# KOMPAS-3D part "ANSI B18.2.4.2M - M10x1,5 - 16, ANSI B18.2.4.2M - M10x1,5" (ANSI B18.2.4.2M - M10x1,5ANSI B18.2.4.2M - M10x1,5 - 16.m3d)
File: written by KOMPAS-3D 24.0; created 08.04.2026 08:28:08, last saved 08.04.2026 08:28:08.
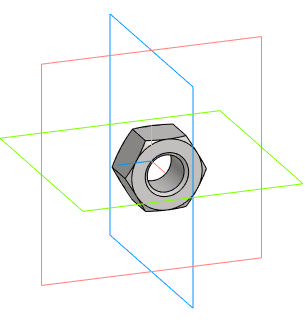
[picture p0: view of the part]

Document properties: Автор: Main; Полное имя файла: D:\DN.ru Аутсерс\Стекло смотровое DN.ru\Исходники\Стекло смотровое DN.ru SG2-34G-F тип В ГОСТ 21836-2021 Ду125 Ру16, углеродистая сталь, фланцевое\ANSI B18.2.4.2M - M10x1,5ANSI B18.2.4.2M - M10x1,5 - 16.m3d

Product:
- Body: Solid1  | qty 1
- Part/product: ANSI B18.2.4.2M - M10x1,5 - 16  | designation ANSI B18.2.4.2M - M10x1,5
    Комментарий: Типы метрических   шестигранных гаек   2
    additional columns: Сталь, мягкая

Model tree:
1. Solid1  (labels: Solid1)

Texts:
  ANSI B18.2.4.2M - M10x1,5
